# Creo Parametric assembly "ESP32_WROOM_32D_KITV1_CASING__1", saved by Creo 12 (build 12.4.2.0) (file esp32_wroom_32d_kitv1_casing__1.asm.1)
Units: Custom; MM, KILOGRAM, SECS

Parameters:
  PTC_WM_ITERATION = "0"
  PTC_WM_VERSION = "-.0"
  PTC_WM_LIFECYCLE_STATE = "In Work"
  PTC_WM_LIFECYCLE = "MO_CADDocument"
  PTC_WM_CREATED_BY = "Maximilian Roepper (Z0017RMS: MO)"
  PTC_WM_CREATED_ON = "18-Sep-26 11:36:42 AM"
  PTC_WM_MODIFIED_BY = "Maximilian Roepper (Z0017RMS: MO)"
  PTC_WM_MODIFIED_ON = "18-Sep-26 11:36:46 AM"
  PDMLINKNUMBER = "PDM000071454994"
  PTC_WM_NUMBER = "PDM000071454994"

Other parameters: WEIGHT, WEIGHT_FACTOR, WEIGHT_ADD, MC_ERRORS, SUPPLIER

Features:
  1. coordinate system
  2. imported feature
  3. component "PCB_PRT_1"
  4. component "SOIC_16_39X99MM_P127MM_PRT_1"
  5. component "SOT_223_PRT_1"
  6. component "USB_C_RECEPTACLE_16P_TOP-1247_1"
  7. component "LED_0603_D2_PRT_1"
  8. component "LED_0603_PWR_PRT_1"
  9. component "SOT_23_1_PRT_1"
  10. component "SOT_23_002_PRT_1"
  11. component "D_SOD_123_PRT_1"
  12. component "RESISTANCES_ASM_ASM_1"
  13. component "CAPACITANCE_ASM_ASM_1"
  14. component "ESP32_WR_32D_MODULE_ASM_ASM_1"
  15. component "ARRAY_ASM_ASM_1"
  16. component "BUTTON_BLACK_001_PRT_1"
  17. component "BUTTON_BLACK_002_PRT_1"
  18. component "PINHEADER_1X15_P254MM_VERTICA_1"
  19. component "PINHEADER_1X15_P254MM_VERTICA_1"

Other named items: DRW_VIEW_ORG, ROUGH-GROB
